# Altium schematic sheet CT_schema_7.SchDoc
size 404 x 379 mm
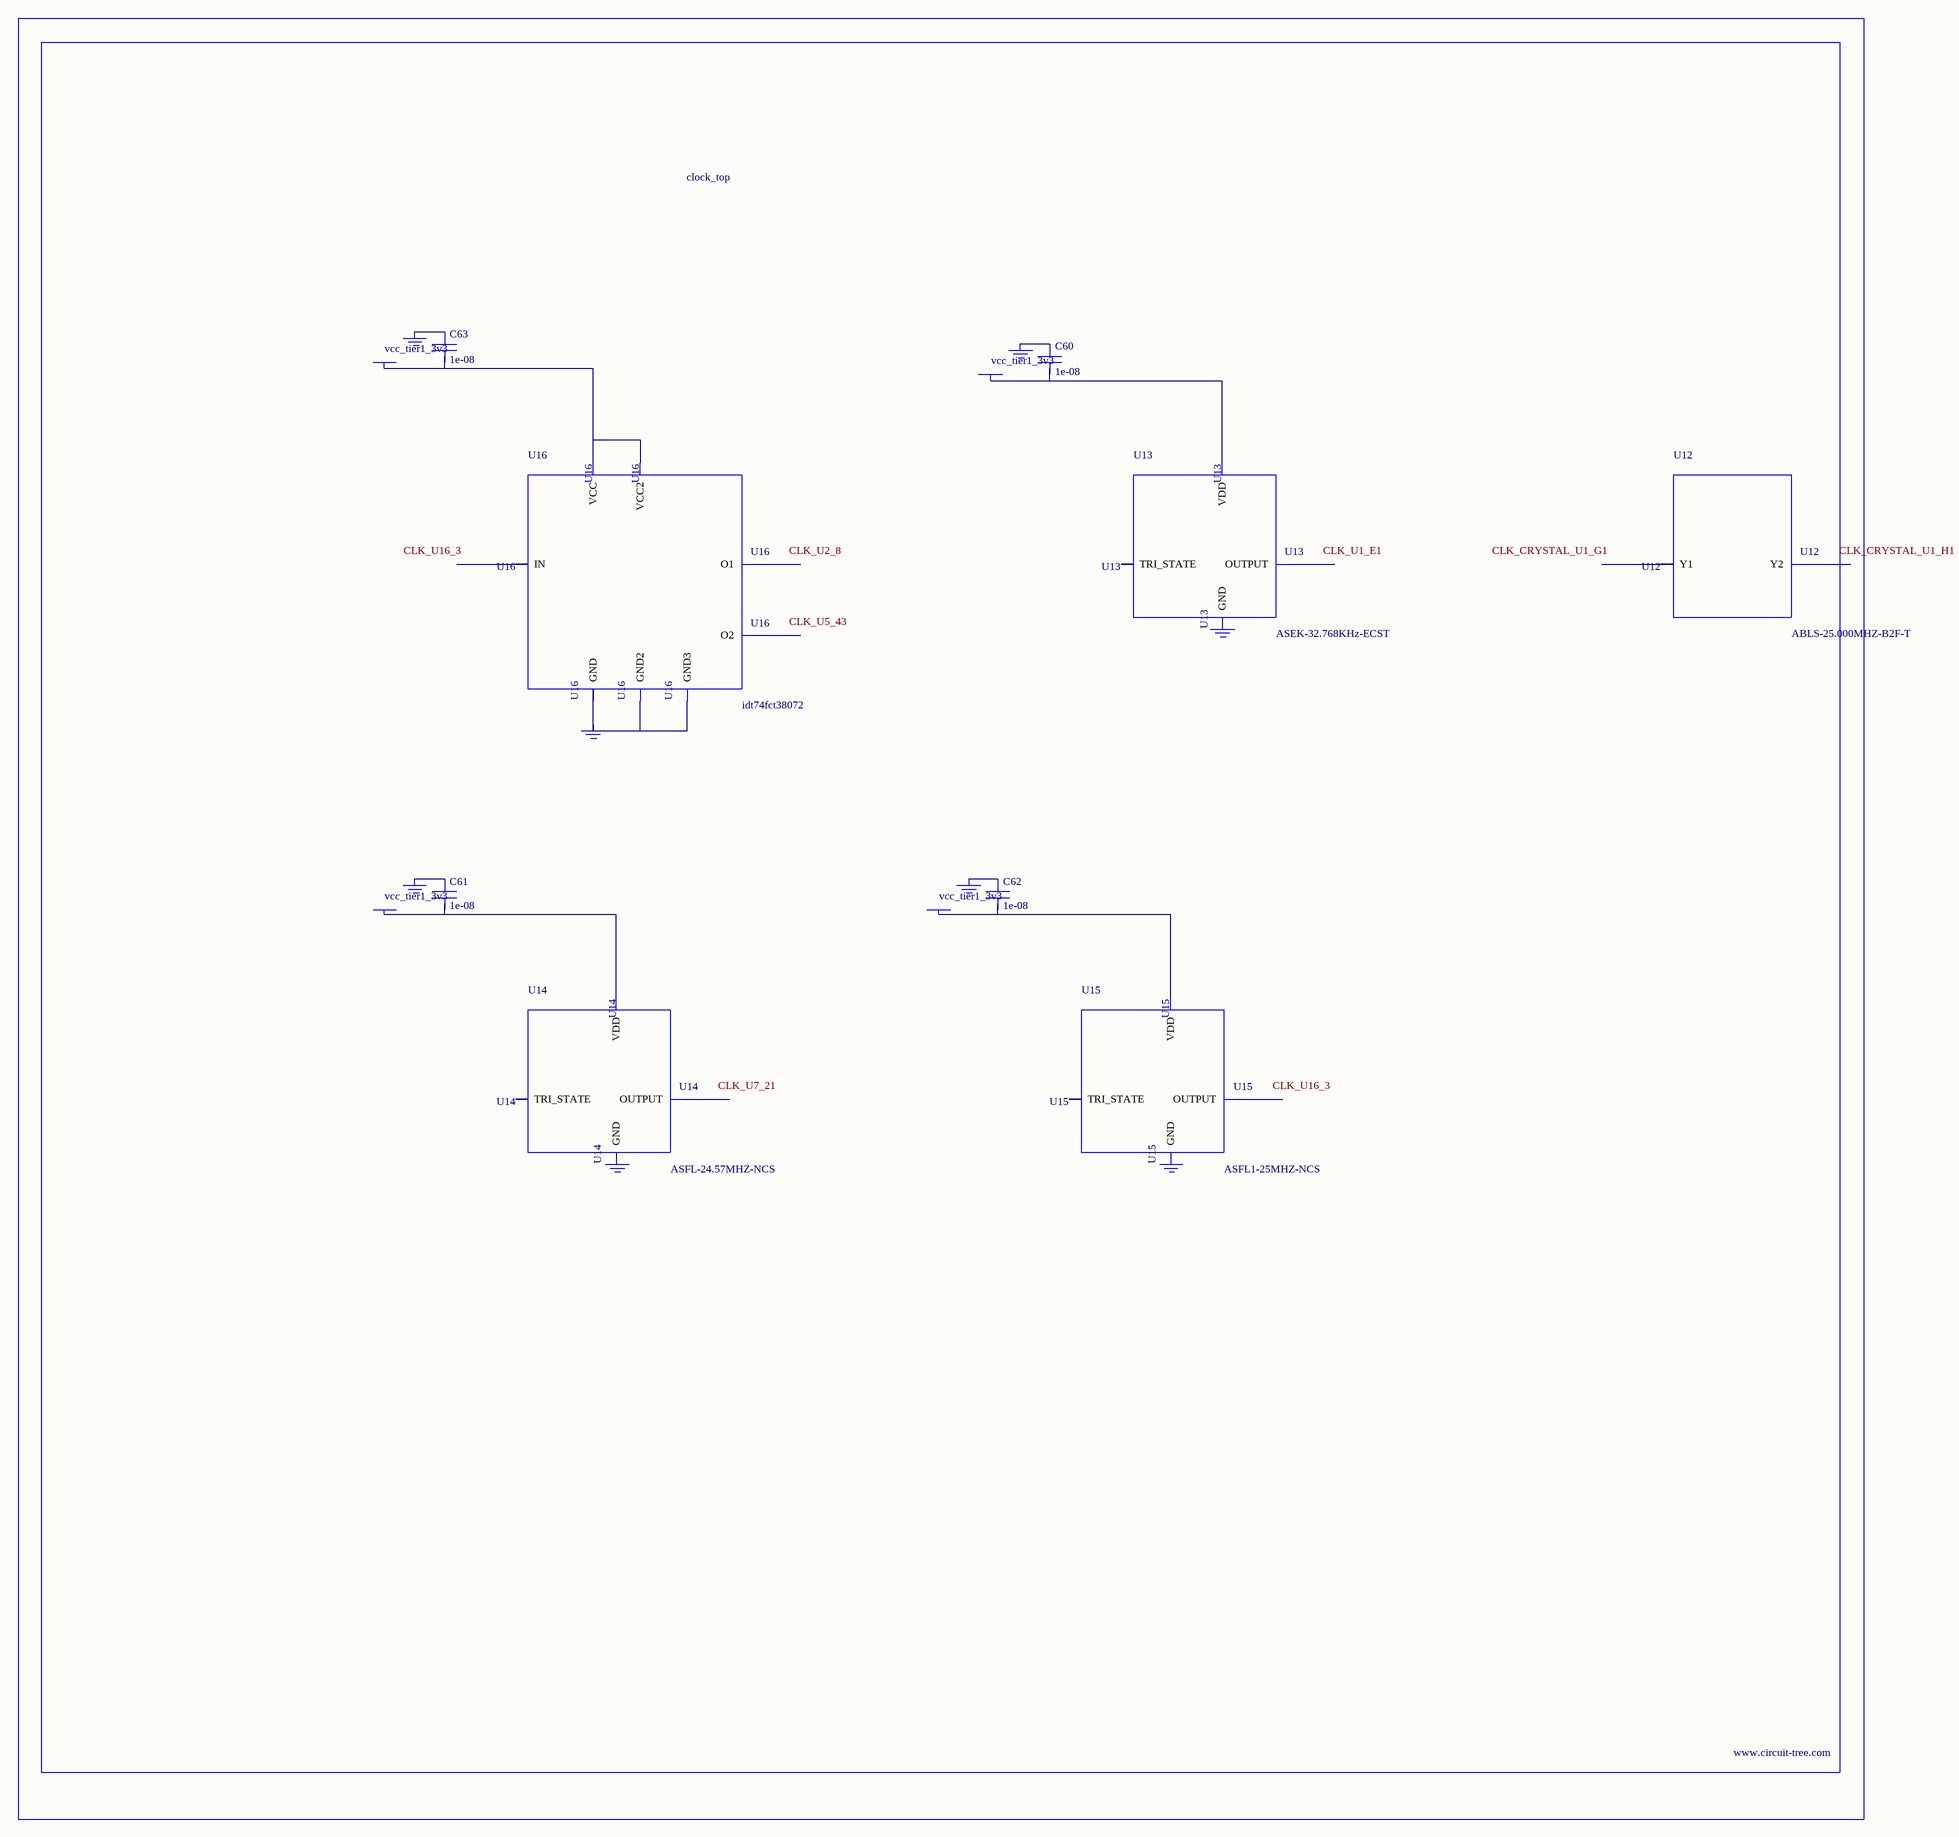
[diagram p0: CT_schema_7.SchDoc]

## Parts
BORDER6  (no value)
C60  1e-08  [C0402]
C61  1e-08  [C0402]
C62  1e-08  [C0402]
C63  1e-08  [C0402]
GND_INSTANCE_6_0  (no value)
GND_INSTANCE_6_1  (no value)
GND_INSTANCE_6_2  (no value)
GND_INSTANCE_6_3  (no value)
GND_INSTANCE_6_4  (no value)
GND_INSTANCE_6_5  (no value)
GND_INSTANCE_6_6  (no value)
GND_INSTANCE_6_7  (no value)
POWER_INSTANCE_6_0  vcc_tier1_3v3
POWER_INSTANCE_6_1  vcc_tier1_3v3
POWER_INSTANCE_6_2  vcc_tier1_3v3
POWER_INSTANCE_6_3  vcc_tier1_3v3
U12  ABLS-25.000MHZ-B2F-T  [ABLS-25.000MHZ-B2F-T]
U13  ASEK-32.768KHz-ECST  [ASEK]
U14  ASFL-24.57MHZ-NCS  [ASFL1]
U15  ASFL1-25MHZ-NCS  [ASFL1]
U16  idt74fct38072  [IDT74FCT38072]

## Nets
NetC60_1: C60.1 GND_INSTANCE_6_0.0(GND)
NetC60_2: C60.2 POWER_INSTANCE_6_0.0(PWR) U13.4(VDD)
NetC61_1: C61.1 GND_INSTANCE_6_2.0(GND)
NetC61_2: C61.2 POWER_INSTANCE_6_1.0(PWR) U14.4(VDD)
NetC62_1: C62.1 GND_INSTANCE_6_4.0(GND)
NetC62_2: C62.2 POWER_INSTANCE_6_2.0(PWR) U15.4(VDD)
NetC63_1: C63.1 GND_INSTANCE_6_6.0(GND)
NetC63_2: C63.2 POWER_INSTANCE_6_3.0(PWR) U16.1(VCC) U16.2(VCC2)
NetGND_INSTANCE_6_7_0: GND_INSTANCE_6_7.0(GND) U16.4(GND) U16.5(GND2) U16.8(GND3)

Not connected (* = marked no-connect by the designer): GND_INSTANCE_6_1 0(GND); GND_INSTANCE_6_3 0(GND); GND_INSTANCE_6_5 0(GND); U12 1(Y1) 2(Y2); U13 1(TRI_STATE) 2(GND) 3(OUTPUT); U14 1(TRI_STATE) 2(GND) 3(OUTPUT); U15 1(TRI_STATE) 2(GND) 3(OUTPUT); U16 3(IN) 6(O2) 7(O1)

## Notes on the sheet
- Labels drawn without touching a wire or pin: CLK_CRYSTAL_U1_G1, CLK_CRYSTAL_U1_H1, CLK_U1_E1, CLK_U2_8, CLK_U5_43, CLK_U7_21, CLK_U16_3

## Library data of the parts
BORDER6 = BORDER_PAGE6
C60-C63 = C0402C103K3RAC
GND_INSTANCE_6_0-GND_INSTANCE_6_7 = GND
POWER_INSTANCE_6_0-POWER_INSTANCE_6_3 = PWR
